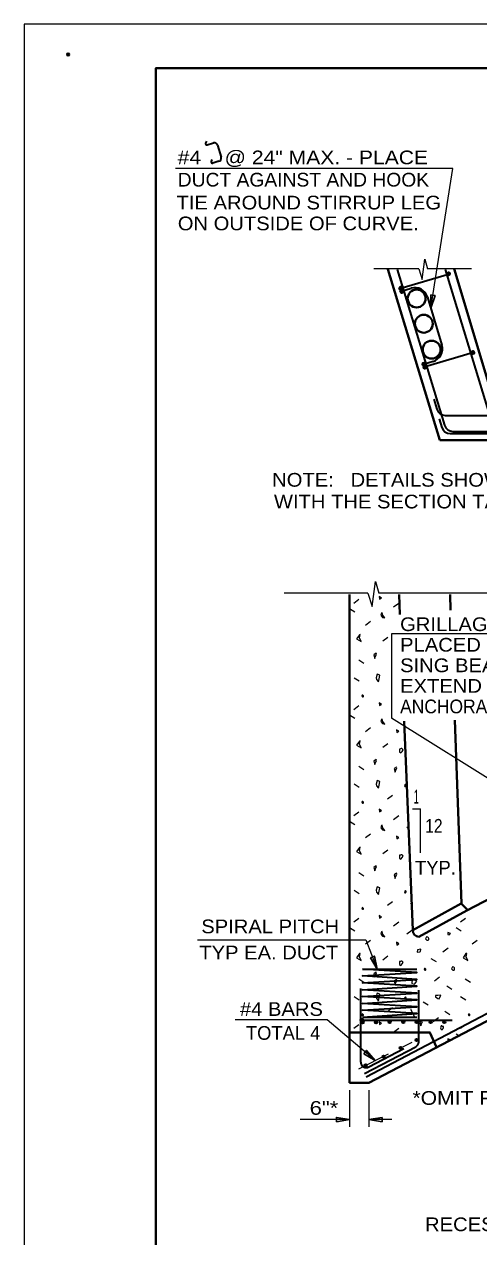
# Model space of a CAD drawing. Extents: x 0 to 22.7, y 0 to 15.6.
# Drawn here: x 0 to 3.45, y 5.45 to 14.67 of the extents above; entities that cross this region are included whole.
import ezdxf
from ezdxf.enums import TextEntityAlignment as Align

# ---------------------------------------------------------------- set-up
doc = ezdxf.new("R2010")
doc.units = 0
doc.header["$LTSCALE"] = 0.042
doc.header["$PDMODE"] = 32
doc.header["$PDSIZE"] = 0.021
doc.linetypes.add('LONG_DASH_SHORT_DASH', pattern=[9.9, 6, -1.2, 1.5, -1.2])
for name, color, linetype, lineweight in [('1', 7, 'Continuous', 13), ('3', 7, 'Continuous', 35), ('4', 7, 'Continuous', 13), ('5', 7, 'LONG_DASH_SHORT_DASH', 13), ('7', 7, 'Continuous', 13)]:
    doc.layers.add(name, color=color, linetype=linetype, lineweight=lineweight)
doc.layers.add('49', color=7, linetype='Continuous')

msp = doc.modelspace()

# ---------------------------------------------------------------- linework, layer by layer
at = {"layer": '1'}
for p, q in [((2.99578, 12.80797), (2.65531, 12.80797)), ((3.39589, 12.80797), (3.06271, 12.80797)), ((3.31917, 12.80797), (3.06271, 12.80797)), ((2.60885, 10.3412), (1.9724, 10.3412)), ((3.56391, 10.3412), (2.69255, 10.3412))]:
    msp.add_line(p, q, dxfattribs=at)
at = {"layer": '1', "lineweight": 40}
for p, q in [((2.76141, 12.80609), (3.15609, 11.50484)), ((3.26516, 12.80797), (3.57865, 11.75974)), ((3.15609, 11.50484), (4.31453, 11.50484)), ((2.46938, 6.61818), (2.46938, 10.33198)), ((2.84589, 10.33198), (2.85208, 10.17922)), ((3.23724, 10.21271), (3.23286, 10.3313)), ((2.885, 9.36802), (2.94943, 7.77896)), ((3.31964, 7.98302), (3.26813, 9.37729)), ((4.86115, 8.7151), (3.35927, 7.92995)), ((2.61615, 6.61818), (6.04656, 8.42313)), ((2.94943, 7.77896), (3.31844, 7.98297)), ((2.99604, 7.72911), (3.35927, 7.92995)), ((3.36583, 7.93563), (3.31844, 7.98297)), ((2.46938, 6.61818), (2.61615, 6.61818))]:
    msp.add_line(p, q, dxfattribs=at)
at = {"layer": '1'}
msp.add_lwpolyline([(0, 0), (22.66667, 0), (22.66667, 14.66667), (0, 14.66667)], close=True, dxfattribs=at)
at = {"layer": '1', "lineweight": 40}
msp.add_lwpolyline([(22.33333, 0.33333), (22.33333, 14.33333), (1, 14.33333), (1, 0.33333)], close=True, dxfattribs=at)
at = {"layer": '1'}
for points in [[(2.99578, 12.80797), (3.02177, 12.72755), (3.04214, 12.88031), (3.06271, 12.80797)], [(2.60885, 10.3412), (2.64141, 10.24057), (2.66688, 10.43167), (2.69255, 10.3412)]]:
    msp.add_lwpolyline(points, dxfattribs=at)
at = {"layer": '1', "lineweight": 40}
msp.add_lwpolyline([(2.46938, 7.00271), (3.07943, 7.00271), (3.13068, 6.89141)], dxfattribs=at)
for centre in [(2.97884, 12.58195), (3.03355, 12.38986), (3.09313, 12.19297)]:
    msp.add_circle(centre, 0.068, dxfattribs=at)
msp.add_arc((3.00031, 7.77899), 0.0509, 180.0392, 265.73939, dxfattribs=at)
at = {"layer": '3'}
for p, q in [((1.38411, 13.77813), (1.37641, 13.76292)), ((1.38938, 13.75), (1.4363, 13.76401)), ((1.46745, 13.74724), (1.49469, 13.65604)), ((1.42458, 13.63885), (1.41807, 13.62391)), ((1.47786, 13.62495), (1.43104, 13.61094)), ((2.83224, 12.80214), (3.1912, 11.61885)), ((2.85896, 12.65927), (3.2287, 12.7699)), ((3.19682, 12.80344), (3.55109, 11.63552)), ((2.86521, 12.63807), (2.93724, 12.65964)), ((3.06172, 12.5925), (3.17073, 12.22797)), ((3.04313, 12.0637), (3.40313, 12.17135)), ((3.10354, 12.10354), (3.03807, 12.08391)), ((3.10948, 11.81755), (3.13286, 11.74042)), ((3.15063, 11.6663), (3.17005, 11.60214)), ((3.19667, 11.69307), (4.31339, 11.69307)), ((3.23391, 11.55484), (4.31339, 11.55484)), ((3.25495, 11.57151), (4.3137, 11.57151)), ((2.59677, 6.66609), (6.04719, 8.48156)), ((2.56818, 7.48391), (2.98104, 7.48391)), ((2.55453, 6.77708), (2.55453, 7.33536)), ((2.99458, 6.93063), (2.99458, 7.32453)), ((2.56818, 7.11932), (2.98104, 7.11932)), ((2.56385, 7.09557), (3.24818, 7.09557)), ((2.58438, 6.68964), (2.97229, 6.89375)), ((2.61563, 6.74021), (2.88281, 6.88078))]:
    msp.add_line(p, q, dxfattribs=at)
msp.add_lwpolyline([(2.56818, 7.11932), (2.98104, 7.14536), (2.56818, 7.17141), (2.98104, 7.19745), (2.56818, 7.22349), (2.98104, 7.24953), (2.56818, 7.27557), (2.98104, 7.30161), (2.56818, 7.32766), (2.98104, 7.3537), (2.56818, 7.37974), (2.98104, 7.40578), (2.56818, 7.43182), (2.98104, 7.45786), (2.56818, 7.48391)], dxfattribs=at)
for centre, radius in [((3.2199, 12.769), 0.0125), ((3.2199, 12.769), 0.00833), ((3.2199, 12.769), 0.00417), ((2.85995, 12.65978), 0.0125), ((2.85995, 12.65978), 0.00833), ((2.86714, 12.63561), 0.0125), ((2.85995, 12.65978), 0.00417), ((2.86714, 12.63561), 0.00833), ((2.86714, 12.63561), 0.00417), ((3.40531, 12.17066), 0.0125), ((3.40531, 12.17066), 0.00833), ((3.40531, 12.17066), 0.00417), ((3.03536, 12.08363), 0.0125), ((3.03536, 12.08363), 0.00833), ((3.03536, 12.08363), 0.00417), ((3.0426, 12.05983), 0.0125), ((3.0426, 12.05983), 0.00833), ((3.0426, 12.05983), 0.00417), ((2.56874, 7.07994), 0.0089), ((2.56874, 7.07994), 0.00593), ((2.56874, 7.07994), 0.00297), ((2.67165, 7.08046), 0.0089), ((2.67165, 7.08046), 0.00593), ((2.67165, 7.08046), 0.00297), ((2.77457, 7.08098), 0.0089), ((2.77457, 7.08098), 0.00593), ((2.77457, 7.08098), 0.00297), ((2.87749, 7.0815), 0.0089), ((2.87749, 7.0815), 0.00593), ((2.87749, 7.0815), 0.00297), ((2.98046, 7.08207), 0.0089), ((2.98046, 7.08207), 0.00593), ((2.98046, 7.08207), 0.00297), ((3.08462, 7.08207), 0.0089), ((3.08462, 7.08207), 0.00593), ((3.08462, 7.08207), 0.00297), ((3.18879, 7.08207), 0.0089), ((3.18879, 7.08207), 0.00593), ((3.18879, 7.08207), 0.00297), ((2.97832, 6.94613), 0.0089), ((2.97832, 6.94613), 0.00593), ((2.97832, 6.94613), 0.00297), ((2.72868, 6.81843), 0.0089), ((2.72868, 6.81843), 0.00593), ((2.72868, 6.81843), 0.00297), ((2.85837, 6.88546), 0.0089), ((2.85837, 6.88546), 0.00593), ((2.85837, 6.88546), 0.00297), ((2.59254, 6.75145), 0.0089), ((2.59254, 6.75145), 0.00593), ((2.59254, 6.75145), 0.00297)]:
    msp.add_circle(centre, radius, dxfattribs=at)
for centre, radius, start, end in [((1.38641, 13.75994), 0.01042, 163.35109, 286.65044), ((1.44345, 13.74004), 0.025, 16.65, 106.65), ((1.47071, 13.6489), 0.025, 286.65, 16.65), ((1.42807, 13.62093), 0.01042, 163.35109, 286.68295), ((2.9659, 12.56385), 0.1, 16.65, 106.65), ((3.07491, 12.19935), 0.1, 286.65, 16.65), ((3.19667, 11.75974), 0.06667, 196.86846, 270), ((3.25497, 11.6382), 0.06667, 196.87338, 270), ((3.23387, 11.62153), 0.06667, 196.87794, 270), ((2.95292, 6.93061), 0.04167, 297.74896, 0), ((2.5962, 6.77708), 0.04167, 180, 297.75176)]:
    msp.add_arc(centre, radius, start, end, dxfattribs=at)
msp.add_point((2.56385, 7.09557), dxfattribs=at)
at = {"layer": '4'}
for p, q in [((4.59969, 8.25786), (2.78911, 9.39073)), ((2.94792, 8.70177), (3.00938, 8.70177)), ((3.00938, 8.36672), (3.00938, 8.70177)), ((2.46938, 6.56458), (2.46938, 6.28375)), ((2.61615, 6.56458), (2.61615, 6.28375)), ((2.46938, 6.33995), (2.09484, 6.33995)), ((2.79089, 6.33995), (2.61615, 6.33995))]:
    msp.add_line(p, q, dxfattribs=at)
for points in [[(3.08719, 12.5074), (3.25516, 13.5712), (1.14703, 13.5712)], [(6.0675, 10.03359), (2.78911, 10.03359), (2.78911, 9.39073)], [(1.31625, 7.70557), (2.59276, 7.70557), (2.67974, 7.48391)], [(2.665, 6.78797), (2.29875, 7.0975), (1.60047, 7.0975)]]:
    msp.add_lwpolyline(points, dxfattribs=at)
at = {"layer": '4', "lineweight": 25}
for points in [[(3.0863, 12.60875), (3.11927, 12.60359), (3.08719, 12.5074)], [(2.62771, 7.57089), (2.65875, 7.58307), (2.67974, 7.48391)], [(2.57786, 6.83979), (2.59938, 6.86526), (2.665, 6.78797)], [(2.36938, 6.32328), (2.36938, 6.35661), (2.46938, 6.33995)], [(2.71615, 6.35661), (2.71615, 6.32328), (2.61615, 6.33995)]]:
    msp.add_lwpolyline(points, close=True, dxfattribs=at)
at = {"layer": '49'}
msp.add_point((0.33333, 14.4375), dxfattribs=at)
at = {"layer": '5'}
msp.add_line((2.54052, 6.72521), (3.00458, 6.95917), dxfattribs=at)
at = {"layer": '7'}
for p, q in [((2.5413, 10.29339), (2.50281, 10.26406)), ((2.84302, 10.26385), (2.80453, 10.23453)), ((2.46938, 10.22411), (2.50896, 10.19911)), ((2.62958, 10.12615), (2.59109, 10.09682)), ((2.76161, 10.00521), (2.72313, 9.97589)), ((2.53979, 9.83464), (2.57938, 9.80979)), ((2.50385, 9.69943), (2.54344, 9.67438)), ((2.46938, 9.41615), (2.50896, 9.39115)), ((2.5413, 9.48542), (2.50281, 9.45615)), ((2.62958, 9.31818), (2.59109, 9.28885)), ((2.76161, 9.19724), (2.72313, 9.16792)), ((2.53979, 9.02667), (2.57938, 9.00182)), ((2.50385, 8.89146), (2.54344, 8.86641)), ((2.79635, 8.80448), (2.75786, 8.77516)), ((2.5413, 8.67745), (2.50281, 8.64818)), ((2.46938, 8.60823), (2.50896, 8.58323)), ((2.84302, 8.64792), (2.80453, 8.61865)), ((2.62958, 8.51021), (2.59109, 8.48094)), ((2.91745, 8.56766), (2.90396, 8.5574)), ((2.76161, 8.38927), (2.72313, 8.36)), ((2.53979, 8.2187), (2.57938, 8.19385)), ((2.50385, 8.08349), (2.54344, 8.05844)), ((2.79635, 7.99651), (2.75786, 7.96719)), ((2.93365, 7.9876), (2.94161, 7.97161)), ((2.5413, 7.86948), (2.50281, 7.84021)), ((2.84302, 7.83995), (2.80453, 7.81068)), ((3.3501, 7.86948), (3.31161, 7.84021)), ((2.46938, 7.80026), (2.50896, 7.77526)), ((2.94245, 7.7787), (2.90396, 7.74943)), ((3.27818, 7.80026), (3.31776, 7.77526)), ((2.62958, 7.70224), (2.59109, 7.67297)), ((3.43839, 7.70224), (3.3999, 7.67297)), ((2.76161, 7.5813), (2.72313, 7.55203)), ((3.08703, 7.56563), (3.12667, 7.54063)), ((3.21745, 7.6425), (3.17896, 7.61323)), ((2.53979, 7.41073), (2.57938, 7.38594)), ((3.1526, 7.42271), (3.11406, 7.39339)), ((3.34859, 7.41073), (3.38813, 7.38594)), ((3.20771, 7.35615), (3.24734, 7.33115)), ((2.50385, 7.27552), (2.54344, 7.25052)), ((3.0276, 7.23625), (3.06719, 7.21125)), ((3.31266, 7.27552), (3.35219, 7.25052)), ((2.79635, 7.18854), (2.75786, 7.15927)), ((2.93365, 7.17969), (2.96297, 7.12083)), ((3.14432, 7.11354), (3.10583, 7.08422)), ((3.19271, 7.16406), (3.23229, 7.13906)), ((2.5413, 7.06156), (2.50281, 7.03224)), ((2.84302, 7.03198), (2.80453, 7.00271)), ((3.3501, 7.06156), (3.31161, 7.03224)), ((3.27818, 6.99229), (3.29849, 6.97948))]:
    msp.add_line(p, q, dxfattribs=at)
for points in [[(2.69359, 10.31599), (2.69656, 10.29531), (2.71135, 10.30422)], [(2.71156, 10.19063), (2.70833, 10.17401), (2.71932, 10.15781), (2.73776, 10.15417), (2.72302, 10.17365), (2.71672, 10.19391)], [(2.54427, 10.02552), (2.5237, 9.99469), (2.55833, 9.97396), (2.54568, 10.00198), (2.55104, 10.02766)], [(2.6538, 9.87281), (2.66292, 9.84625), (2.66292, 9.84906), (2.67474, 9.8787), (2.67172, 9.88458)], [(2.67969, 9.72531), (2.67073, 9.6988), (2.67531, 9.68557), (2.68854, 9.66786), (2.69437, 9.69146), (2.69885, 9.71802)], [(2.56646, 9.56703), (2.56276, 9.55891), (2.56708, 9.55443), (2.5724, 9.55443), (2.57458, 9.55677), (2.57458, 9.56109), (2.57385, 9.56323), (2.57156, 9.56563)], [(2.69359, 9.50802), (2.69656, 9.48734), (2.71135, 9.49625)], [(2.71156, 9.38266), (2.70833, 9.36604), (2.71932, 9.34984), (2.73776, 9.3462), (2.72302, 9.36573), (2.71672, 9.38594)], [(2.54427, 9.2176), (2.5237, 9.18672), (2.55833, 9.16599), (2.54568, 9.19401), (2.55104, 9.21969)], [(2.82688, 9.30344), (2.8299, 9.28281), (2.84469, 9.29167)], [(2.84818, 9.15698), (2.84818, 9.13469), (2.85828, 9.1275), (2.86135, 9.13036), (2.87005, 9.13927), (2.87594, 9.15109), (2.87167, 9.15698), (2.86573, 9.15984), (2.86286, 9.15984), (2.85708, 9.15823)], [(2.6538, 9.06484), (2.66292, 9.03828), (2.66292, 9.04115), (2.67474, 9.07073), (2.67172, 9.07661)], [(2.80755, 9.00828), (2.81667, 8.98172), (2.81667, 8.98458), (2.82844, 9.01417), (2.82547, 9.02005)], [(2.67969, 8.9174), (2.67073, 8.89083), (2.67531, 8.8776), (2.68854, 8.8599), (2.69437, 8.88349), (2.69885, 8.91005)], [(2.88802, 8.87958), (2.89036, 8.87219), (2.8925, 8.87219), (2.89547, 8.87292), (2.89766, 8.8751), (2.89979, 8.87958), (2.89917, 8.88396), (2.89547, 8.88474), (2.89391, 8.88625), (2.89099, 8.88625)], [(2.56646, 8.75906), (2.56276, 8.75094), (2.56708, 8.74646), (2.5724, 8.74646), (2.57458, 8.7488), (2.57458, 8.75313), (2.57385, 8.75526), (2.57156, 8.75766)], [(2.69359, 8.70005), (2.69656, 8.67938), (2.71135, 8.68828)], [(2.71156, 8.57469), (2.70833, 8.55813), (2.71932, 8.54188), (2.73776, 8.53823), (2.72302, 8.55776), (2.71672, 8.57802)], [(2.82688, 8.49547), (2.8299, 8.47484), (2.84469, 8.4837)], [(2.54427, 8.40964), (2.5237, 8.37875), (2.55833, 8.35802), (2.54568, 8.38604), (2.55104, 8.41177)], [(2.84818, 8.34906), (2.84818, 8.32672), (2.85828, 8.31953), (2.86135, 8.3224), (2.87005, 8.3313), (2.87594, 8.34313), (2.87167, 8.34906), (2.86573, 8.35187), (2.86286, 8.35187), (2.85708, 8.35026)], [(2.6538, 8.25688), (2.66292, 8.23031), (2.66292, 8.23318), (2.67474, 8.26276), (2.67172, 8.26865)], [(2.80755, 8.20031), (2.81667, 8.17375), (2.81667, 8.17661), (2.82844, 8.20625), (2.82547, 8.21208)], [(2.67969, 8.10943), (2.67073, 8.08292), (2.67531, 8.06964), (2.68854, 8.05193), (2.69437, 8.07552), (2.69885, 8.10208)], [(2.88802, 8.07161), (2.89036, 8.06422), (2.8925, 8.06422), (2.89547, 8.065), (2.89766, 8.06714), (2.89979, 8.07161), (2.89917, 8.07604), (2.89547, 8.07677), (2.89391, 8.07833), (2.89099, 8.07833)], [(2.56646, 7.95109), (2.56276, 7.94302), (2.56708, 7.93849), (2.5724, 7.93849), (2.57458, 7.94083), (2.57458, 7.94521), (2.57385, 7.94729), (2.57156, 7.94969)], [(2.69359, 7.89208), (2.69656, 7.87146), (2.71135, 7.88031)], [(2.71156, 7.76677), (2.70833, 7.75016), (2.71932, 7.73391), (2.73776, 7.73026), (2.72302, 7.74979), (2.71672, 7.77005)], [(3.21708, 7.76234), (3.21641, 7.74656), (3.22594, 7.74432), (3.23516, 7.755)], [(2.82688, 7.6875), (2.8299, 7.66688), (2.84469, 7.67573)], [(3.05474, 7.72906), (3.04734, 7.71292), (3.05599, 7.70391), (3.06656, 7.70391), (3.07094, 7.70859), (3.07094, 7.71724), (3.06948, 7.72146), (3.0649, 7.72625)], [(2.54427, 7.60167), (2.5237, 7.57083), (2.55833, 7.55005), (2.54568, 7.57813), (2.55104, 7.6038)], [(2.98516, 7.63021), (2.98219, 7.61255), (3.00286, 7.61552), (3.0087, 7.61844), (3.01167, 7.63609)], [(3.35307, 7.60167), (3.3325, 7.57083), (3.36714, 7.55005), (3.35448, 7.57813), (3.35979, 7.6038)], [(2.84818, 7.54109), (2.84818, 7.51875), (2.85828, 7.51156), (2.86135, 7.51448), (2.87005, 7.52333), (2.87594, 7.53516), (2.87167, 7.54109), (2.86573, 7.54391), (2.86286, 7.54391), (2.85708, 7.54229)], [(3.04, 7.48958), (3.0363, 7.48146), (3.04063, 7.47698), (3.04594, 7.47698), (3.04807, 7.47932), (3.04807, 7.48365), (3.04734, 7.48578), (3.04505, 7.48813)], [(3.25156, 7.50208), (3.24417, 7.48594), (3.25281, 7.47693), (3.26344, 7.47693), (3.26776, 7.48161), (3.26776, 7.49026), (3.2663, 7.49448), (3.26172, 7.49927)], [(2.6538, 7.44896), (2.66292, 7.42234), (2.66292, 7.42521), (2.67474, 7.45479), (2.67172, 7.46068)], [(2.80755, 7.3924), (2.81667, 7.36583), (2.81667, 7.36865), (2.82844, 7.39828), (2.82547, 7.40417)], [(2.94464, 7.40646), (2.94323, 7.37479), (2.96234, 7.37031), (2.98073, 7.39167)], [(2.67969, 7.30146), (2.67073, 7.27495), (2.67531, 7.26167), (2.68854, 7.24396), (2.69437, 7.26755), (2.69885, 7.29411)], [(3.13943, 7.28391), (3.12177, 7.2824), (3.12177, 7.27359), (3.14094, 7.26036), (3.1513, 7.25885), (3.16161, 7.28682)], [(2.88802, 7.26365), (2.89036, 7.25625), (2.8925, 7.25625), (2.89547, 7.25703), (2.89766, 7.25917), (2.89979, 7.26365), (2.89917, 7.26807), (2.89547, 7.2688), (2.89391, 7.27036), (2.89099, 7.27036)], [(2.56646, 7.14313), (2.56276, 7.13505), (2.56708, 7.13052), (2.5724, 7.13052), (2.57458, 7.13292), (2.57458, 7.13724), (2.57385, 7.13938), (2.57156, 7.14172)], [(3.37526, 7.14313), (3.37156, 7.13505), (3.37589, 7.13052), (3.3812, 7.13052), (3.38339, 7.13292), (3.38339, 7.13724), (3.38266, 7.13938), (3.38036, 7.14172)], [(2.69359, 7.08417), (2.69656, 7.06349), (2.71135, 7.0724)], [(3.00245, 7.07984), (3.01156, 7.05323), (3.01156, 7.05609), (3.02333, 7.08573), (3.02031, 7.09156)], [(3.15974, 7.03844), (3.16438, 7.0237), (3.16865, 7.0237), (3.17464, 7.02516), (3.17896, 7.02948), (3.18328, 7.03844), (3.18208, 7.04719), (3.17464, 7.04875), (3.17151, 7.05177), (3.16563, 7.05177)]]:
    msp.add_lwpolyline(points, close=True, dxfattribs=at)
for points in [[(3.21708, 6.95438), (3.21641, 6.93859), (3.21932, 6.93792)], [(3.23391, 6.94557), (3.23516, 6.94703), (3.21708, 6.95438)]]:
    msp.add_lwpolyline(points, dxfattribs=at)

# ---------------------------------------------------------------- texts
at = {"layer": '4'}
for s, height, width, p in [('#4    @ 24" MAX. - PLACE', 0.1041, 1.15, (1.16484, 13.60234)), ('DUCT AGAINST AND HOOK', 0.1041, 1.05, (1.16505, 13.43302)), ('TIE AROUND STIRRUP LEG', 0.1041, 1.1, (1.15646, 13.2588)), ('ON OUTSIDE OF CURVE.', 0.1041, 1.1, (1.16578, 13.10047)), ('NOTE:   DETAILS SHOWN ARE FOR A CURVE TO THE RIGHT', 0.1041, 1.1, (1.88214, 11.15135)), ('WITH THE SECTION TAKEN LOOKING AHEAD ON STATION.', 0.1041, 1.1, (1.89573, 10.9862)), ('GRILLAGE - #4 @ 4" BOTH WAYS,  TO BE', 0.1042, 1.1, (2.85354, 10.0537)), ('PLACED 1" MAX. CLEAR FROM PRESTRES-', 0.1042, 1.1, (2.85354, 9.89745)), ('SING BEARING PLATE AT EACH GIRDER.', 0.1042, 1.1, (2.85354, 9.7412)), ('EXTEND 6" BEYOND RECESS FOR', 0.1042, 1.1, (2.85354, 9.58495)), ('ANCHORAGE.', 0.1042, 0.95, (2.85354, 9.4287)), ('1', 0.1042, 0.5, (2.95755, 8.74276)), ('12', 0.1042, 0.85, (3.04432, 8.52099)), ('*OMIT FOR SKEW >20°', 0.1041, 1.15, (2.9474, 6.45234)), ('RECESS FOR ANCHORAGE SHALL BE', 0.1042, 1.1, (3.04286, 5.49167))]:
    msp.add_text(s, height=height, dxfattribs=dict(at, width=width)).set_placement(p)
msp.add_text('TYP.', height=0.1042, dxfattribs=at).set_placement((2.96719, 8.20276))
for s, width, p in [('SPIRAL PITCH', 1.1, (2.39052, 7.75646)), ('TYP EA. DUCT', 1.1, (2.38422, 7.55807)), ('#4 BARS', 1.1, (2.26729, 7.12833)), ('6"*', 1.2, (2.38396, 6.37646))]:
    msp.add_text(s, height=0.1041, dxfattribs=dict(at, width=width)).set_placement(p, align=Align.RIGHT)
msp.add_text('TOTAL 4', height=0.1041, dxfattribs=at).set_placement((2.24766, 6.94646), align=Align.RIGHT)

doc.saveas('drawing.dxf')
